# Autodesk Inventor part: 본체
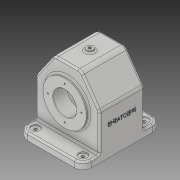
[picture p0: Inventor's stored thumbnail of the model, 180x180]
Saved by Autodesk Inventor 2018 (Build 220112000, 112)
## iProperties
Created: 2022-12
Part Number: 본체
Material: 일반
Document SubType Name: Modeling
Designer: 강의실04
Density: 1 g/cm^3
Appearance: 기본값
Author: 강의실04
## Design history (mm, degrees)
sketch "스케치1"
  geometry: L1 (-55, 12)-(55, 12); L2 (55, 12)-(55, -65); L3 (55, -65)-(-55, -65); L4 (-55, -65)-(-55, 12); L5 (-55, 12)-(-23.491, 57); L6 (-23.491, 57)-(23.491, 57); L7 (23.491, 57)-(55, 12); 3 further points
  constraints: 14 end point, 2 horizontal, 2 midpoint, 2 parallel, 2 vertical alignment, 1 perpendicular
  dimensions: "d1" = 65 distance from line of L3 point (0, 0); "d2" = 77 distance of L3.end L1.start; "d3" = 110 distance of L2.end L3.end; "d4" = 35 deg angle of L5 L4; "d5" = 122 distance between parallel lines of L3 L6
extrude "돌출1" new body sketch "스케치1" stored distance "d6" = 77; taper "d7" = 0 deg
feature "쉘1" dims "d8" = 5
sketch "스케치2"
  geometry: L1 (5, -5)-(5, -72) reference; L2 (5, -72)-(105, -72) reference; L3 (105, -72)-(105, -5) reference; L4 (105, -5)-(5, -5) reference; L5 (0, -77)-(0, 0) reference; L6 (0, 0)-(110, 0) reference; L7 (110, 0)-(110, -77) reference; L8 (110, -77)-(0, -77) reference; L9 (0, -105.5)-(110, -105.5); L10 (110, -105.5)-(110, 28.5); L11 (110, 28.5)-(0, 28.5); L12 (0, 28.5)-(0, -105.5); L13 (0, -105.5)-(110, 28.5); L14 (110, -105.5)-(0, 28.5); 1 further point
  constraints: 12 end point, 2 midpoint, 2 parallel, 1 horizontal, 1 perpendicular, 1 point on line
  dimensions: "d9" = 134 distance of L9.end L10.end
extrude "돌출2" join sketch "스케치2" distance "d10" = 12; taper "d11" = 0 deg
node "작업 평면1"
sketch "스케치3"
  geometry: C1 r 6 at (0, 0); 1 further point
  constraints: 1 centre point, 1 coincident
  dimensions: "d13" = 12 diameter of C1
extrude "돌출3" join sketch "스케치3" stored distance "d14" = 12; taper "d15" = 0 deg
sketch "스케치4"
  geometry: 1 further point
hole "구멍1" sketch "스케치4" at (0, 0) diameter "d16" = 5.188; stored, may be unused: countersink angle "d20" = 90 deg, drill point angle "d22" = 118 deg; dims "d17" = 12, "d18" = 4, "d19" = 2, "d21" = 16
sketch "스케치5"
  geometry: C1 r 37.5 at (0, 0); 1 further point
  constraints: 1 centre point, 1 coincident
  dimensions: "d23" = 75 diameter of C1
extrude "돌출4" join sketch "스케치5" distance "d24" = 5; taper "d25" = 0 deg
sketch "스케치6"
  geometry: C1 r 31 at (0, 0); 1 further point
  constraints: 1 centre point, 1 coincident
  dimensions: "d26" = 62 diameter of C1
extrude "돌출5" join sketch "스케치6" distance "d27" = 10; taper "d28" = 0 deg
sketch "스케치7"
  geometry: L1 (10.424, 33.5)-(-65, 33.5) reference; L2 (0, 33.5)-(0, 0); L3 (52, 33.5)-(10.424, 33.5) reference; L4 (41, 33.5)-(27, 19.5); L5 (27, 19.5)-(0, 19.5); L6 (37.5, 43.5)-(-37.5, 43.5) reference; L7 (41, 33.5)-(0, 33.5)
  constraints: 8 end point, 3 point on line, 2 perpendicular, 1 vertical
  dimensions: "d29" = 54 diameter of L4.end L2; "d30" = 135 deg angle of L3 L4; "d31" = 24 distance between parallel lines of L5 L6
revolve "회전1" sketch "스케치7" stored, may be unused: angle "d32" = 90 deg
sketch "스케치8"
  geometry: C1 r 20 at (0, 0); 1 further point
  constraints: 1 centre point, 1 coincident
  dimensions: "d33" = 40 diameter of C1
extrude "돌출6" cut sketch "스케치8" extent not by distance; stored distance "d34" = 10; taper "d35" = 0 deg
sketch "스케치9" dims "d36" = 58
  geometry: 3 further points
  constraints: 2 vertical alignment, 1 coincident, 2 other
hole "구멍2" sketch "스케치9" at (0, 29) diameter "d37" = 2.459; stored, may be unused: countersink angle "d41" = 90 deg, drill point angle "d43" = 118 deg; dims "d38" = 6, "d39" = 4, "d40" = 2, "d42" = 8
sketch "스케치10" dims "d47" = 52
  geometry: 3 further points
  constraints: 2 vertical alignment, 1 coincident, 2 other
hole "구멍3" sketch "스케치10" at (0, 26) diameter "d48" = 2.459; stored, may be unused: countersink angle "d52" = 90 deg, drill point angle "d54" = 118 deg; dims "d49" = 6, "d50" = 4, "d51" = 2, "d53" = 8
fillet "모깎기1" dims "d58" = 14
sketch "스케치11"
  geometry: L1 (14, 105.5)-(96, 105.5) reference; L2 (110, 91.5)-(110, 77) reference; L3 (110, 77)-(110, 0) reference; L4 (110, 0)-(0, 0) reference; L5 (0, -14.5)-(0, 0) reference; L6 (96, -28.5)-(14, -28.5) reference; L7 (110, 0)-(110, -14.5) reference; L8 (0, 77)-(0, 91.5) reference; L9 (0, 77)-(110, 77) reference; L10 (0, 0)-(0, 77) reference; L11 (105, 5)-(105, 72) reference; L12 (105, 72)-(5, 72) reference; L13 (5, 72)-(5, 5) reference; L14 (5, 5)-(105, 5) reference; A1 r 14 centre (14, 91.5) between (14, 105.5) and (0, 91.5) reference; A2 r 14 centre (96, 91.5) between (110, 91.5) and (96, 105.5) reference; A3 r 14 centre (14, -14.5) between (0, -14.5) and (14, -28.5) reference; A4 r 14 centre (96, -14.5) between (96, -28.5) and (110, -14.5) reference; 1 further point
hole "구멍4" sketch "스케치11" at (14, -14.5), (96, -14.5), (14, 91.5), (96, 91.5) diameter "d59" = 5.5; stored, may be unused: countersink angle "d63" = 90 deg, drill point angle "d65" = 118 deg; dims "d60" = 6, "d61" = 15, "d62" = 2, "d64" = 8
node "작업 평면2"
sketch "스케치12"
  geometry: L1 (-14.5, -77)-(-28.5, -77) reference; 2 further points
  constraints: 1 vertical alignment, 1 other
  dimensions: "d67" = 50 distance from line of L1 point (38.5, -27)
feature "엠보싱1" sketch "스케치12" dims "d1" = 65, "d2" = 77, "d3" = 110, "d4" = 35 deg, "d5" = 122, "d9" = 134, "d68" = 0.5, "d69" = 0
fillet "모깎기2" dims "d70" = 3
fillet "모깎기3" dims "d71" = 5
fillet "모깎기4" dims "d72" = 3
fillet "모깎기5" dims "d73" = 10
fillet "모깎기6" dims "d74" = 3
fillet "모깎기7" dims "d75" = 3
chamfer "모따기1" distance "d76" = 1; stored, may be unused: second distance "d77" = 2, angle "d78" = 45 deg
node "솔리드1"
pattern_circular "원형 패턴1" dims angle "d45" = 360 deg
pattern_circular "원형 패턴2" dims angle "d56" = 360 deg
node "절단 모서리 투영1"
node "절단 모서리 투영2"
other parameters: "d12" = 61, "d66" = 12.5
